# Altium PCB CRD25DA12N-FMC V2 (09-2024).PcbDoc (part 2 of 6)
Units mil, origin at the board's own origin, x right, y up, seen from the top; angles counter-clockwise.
Board outline 8000 x 8000 mil, 6 copper layers (Top Layer, Layer 2, Layer 3, Layer 4, Layer 5, Bottom Layer), stack 91 mil thick; 602 components, 333 nets, 1670 pads, 639 vias.
Unrouted connection lines stored in the file: 1.
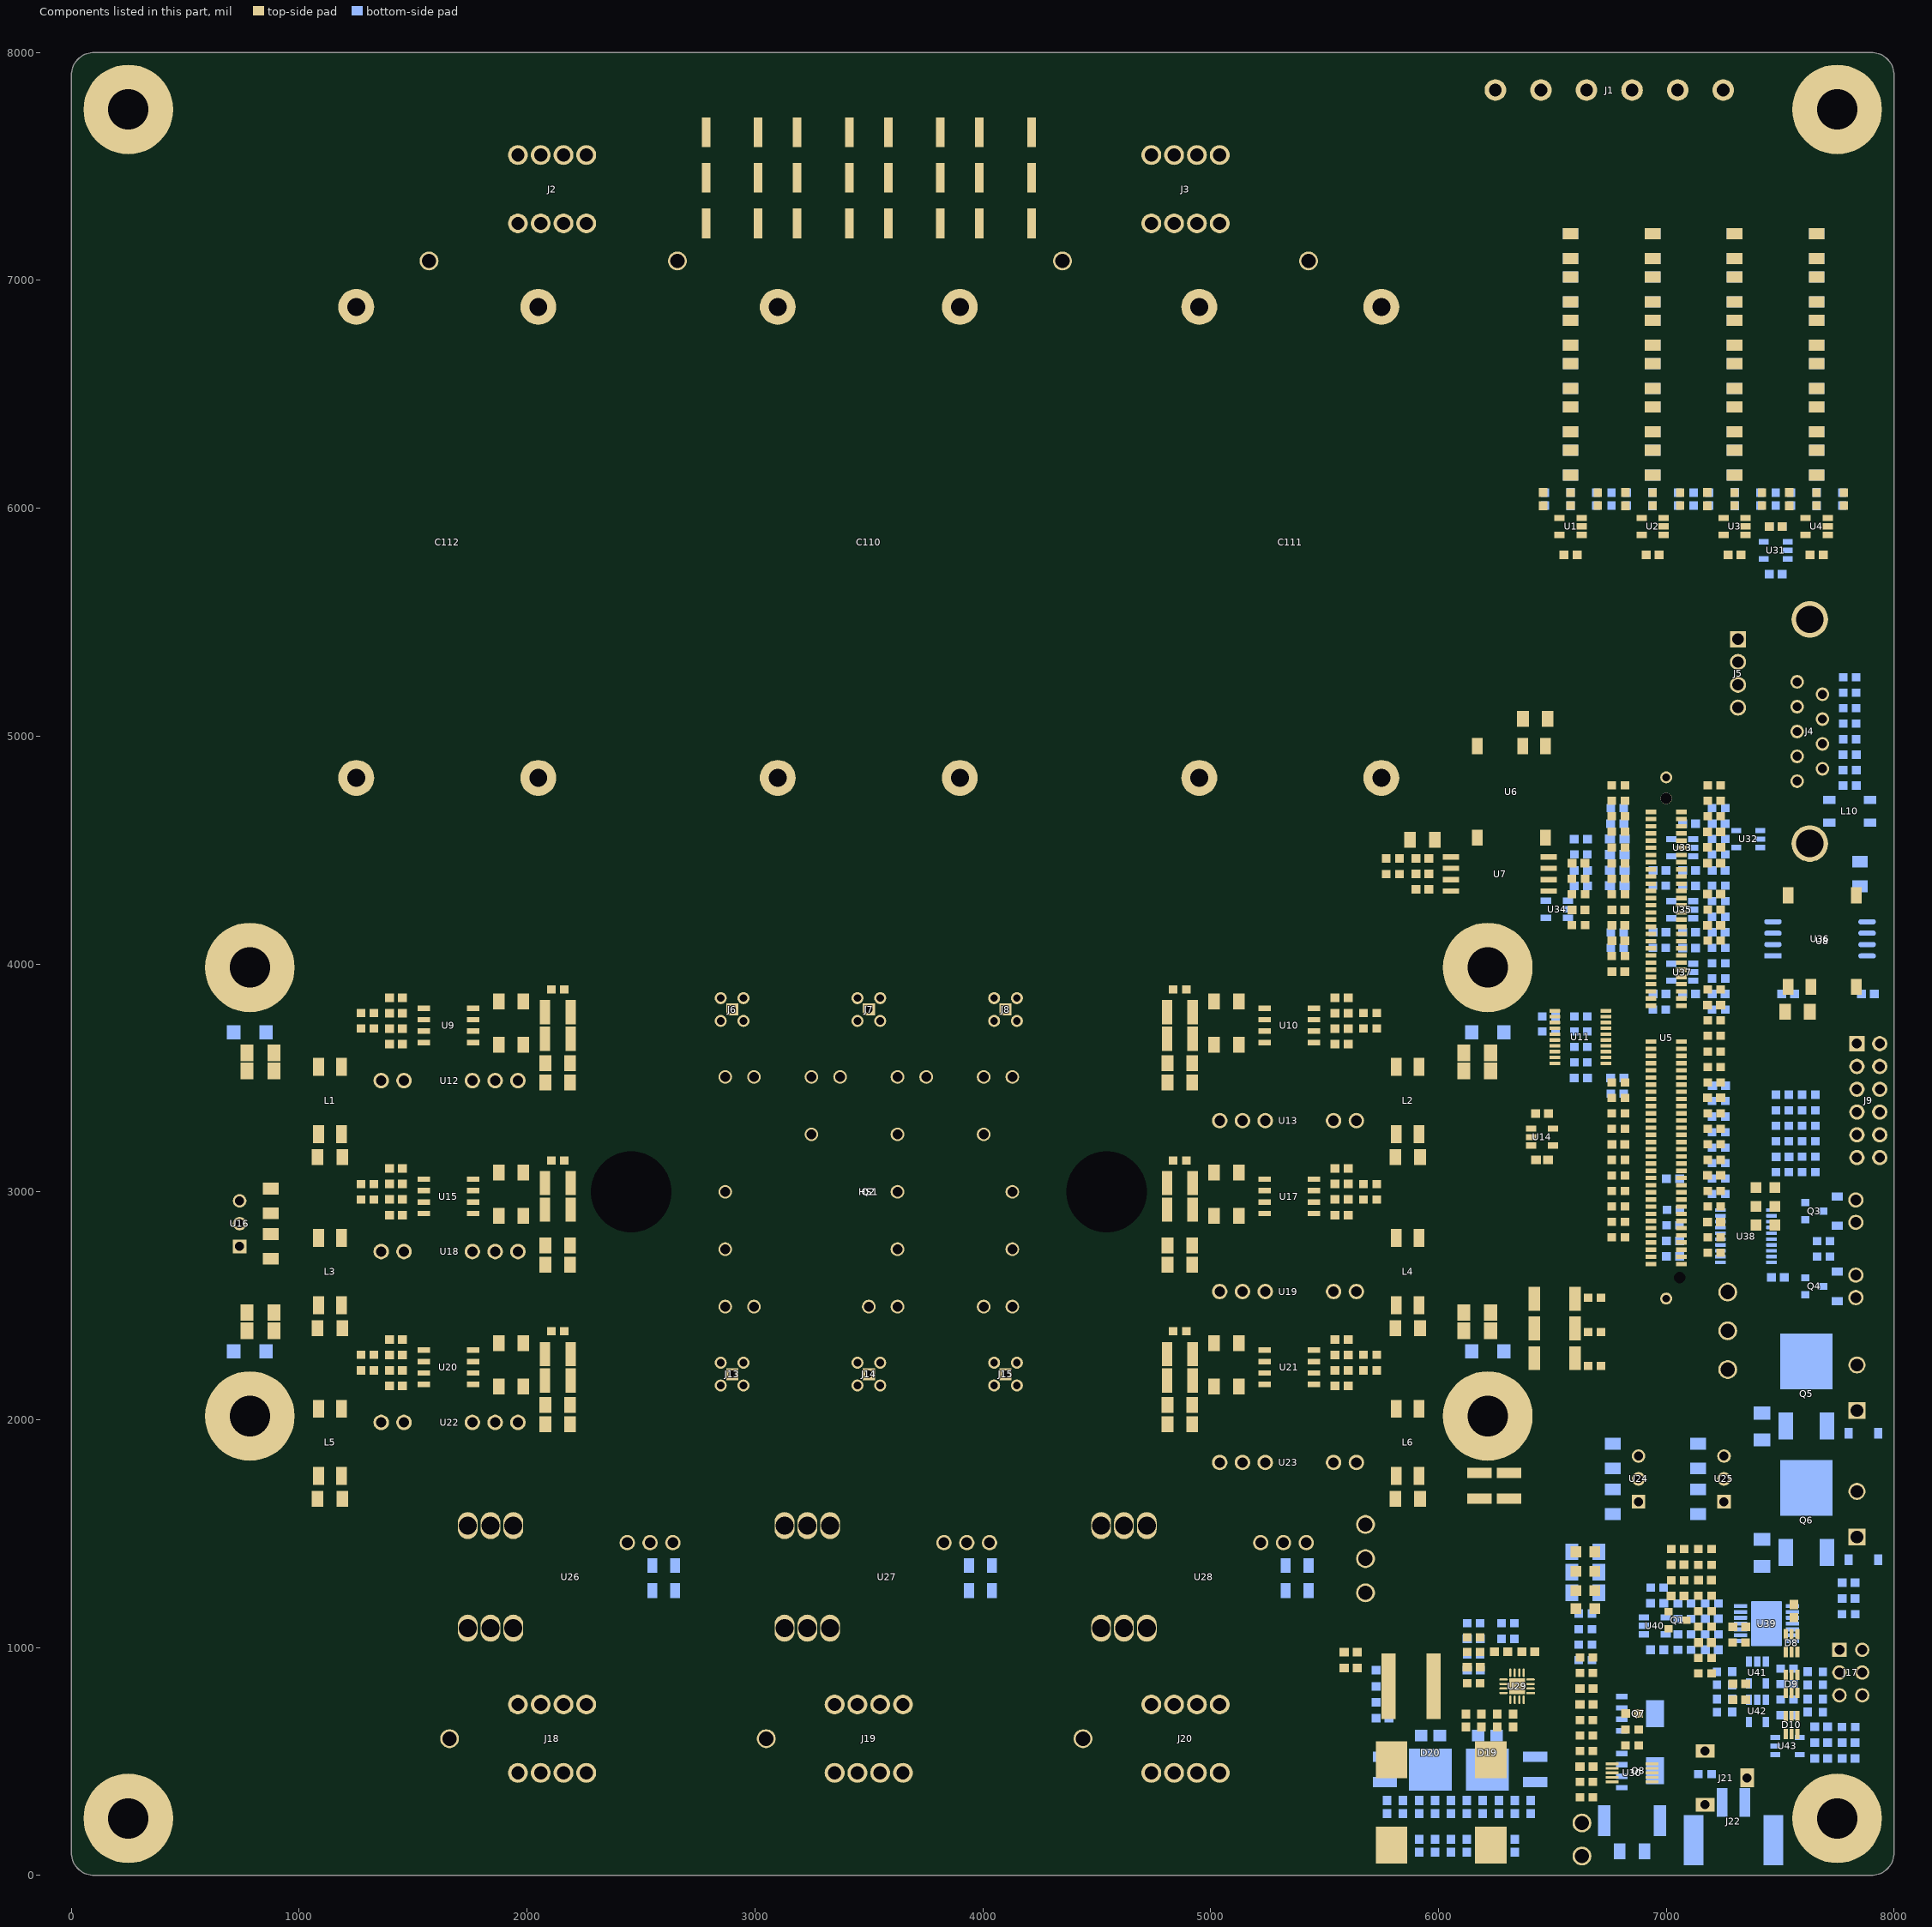
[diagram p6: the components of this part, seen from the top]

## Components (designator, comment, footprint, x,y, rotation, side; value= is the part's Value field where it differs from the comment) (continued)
R196 "RC0603JR-07120RL" FP-MCR03-IPC_B 7805,4986 r0 bottom value=120Ω
R197 "ERJ3EKF1002V" FP-MCR03-IPC_B 7230,4684 r180 bottom value=10kΩ
R198 "ERJ3EKF1002V" FP-MCR03-IPC_B 6785,4684 r0 bottom value=10kΩ
R199 "RT0603DRD071K4L" FP-MCR03-IPC_B 7230,4548 r180 bottom value=1.4kΩ
R200 "RMCF0603FT7K15" FP-MCR03-IPC_B 7230,4480 r180 bottom value=7.15kΩ
R201 "ERA3AEB4021V" FP-MCR03-IPC_B 6625,4480 r0 bottom value=4.02kΩ
R202 "ERA3AEB4021V" FP-MCR03-IPC_B 7230,4343 r0 bottom value=4.02kΩ
R203 "RC0603FR-077K87L" FP-MCR03-IPC_B 6970,4343 r0 bottom value=7.87kΩ
R204 "RT0603DRD071K4L" FP-MCR03-IPC_B 7230,4275 r180 bottom value=1.4kΩ
R205 "RMCF0603FT7K15" FP-MCR03-IPC_B 7230,4207 r180 bottom value=7.15kΩ
R206 "ERJ-3EKF49R9V" FP-MCR03-IPC_B 6785,4139 r0 bottom value=49.9Ω
R207 "ERA3AEB4021V" FP-MCR03-IPC_B 7230,4070 r0 bottom value=4.02kΩ
R208 "RC0603FR-077K87L" FP-MCR03-IPC_B 6970,4070 r0 bottom value=7.87kΩ
R209 "ERJ-3EKF49R9V" FP-MCR03-IPC_B 6785,4070 r0 bottom value=49.9Ω
R210 "RT0603DRD071K4L" FP-MCR03-IPC_B 7230,4003 r180 bottom value=1.4kΩ
R211 "RMCF0603FT7K15" FP-MCR03-IPC_B 7230,3936 r180 bottom value=7.15kΩ
R212 "ERA3AEB4021V" FP-MCR03-IPC_B 7230,3800 r0 bottom value=4.02kΩ
R213 "RC0603FR-077K87L" FP-MCR03-IPC_B 6970,3800 r0 bottom value=7.87kΩ
R214 "RC0603FR-07100KL" FP-MCR03-IPC_B 6625,3770 r180 bottom value=100kΩ
R215 "RC0603FR-07100KL" FP-MCR03-IPC_B 6485,3770 r180 bottom value=100kΩ
R216 "RC0603FR-07100KL" FP-MCR03-IPC_B 6625,3703 r180 bottom value=100kΩ
R217 "RC0603FR-07100KL" FP-MCR03-IPC_B 6485,3703 r180 bottom value=100kΩ
R218 "RC0603FR-07100KL" FP-MCR03-IPC_B 6625,3636 r180 bottom value=100kΩ
R219 "RC0603FR-07100KL" FP-MCR03-IPC_B 6625,3568 r180 bottom value=100kΩ
R220 "ERJ3EKF1002V" FP-MCR03-IPC_B 6785,3430 r180 bottom value=10kΩ
R221 "RC0603FR-13330RL" FP-MCR03-IPC_B 7625,3426 r180 bottom value=330Ω
R222 "RC0603FR-13330RL" FP-MCR03-IPC_B 7510,3426 r180 bottom value=330Ω
R223 "ERJ3EKF1002V" FP-MCR03-IPC_B 7230,3398 r180 bottom value=10kΩ
R224 "RC0603FR-13330RL" FP-MCR03-IPC_B 7625,3358 r180 bottom value=330Ω
R225 "RC0603FR-13330RL" FP-MCR03-IPC_B 7510,3358 r180 bottom value=330Ω
R226 "CRCW06030000Z0EB" FP-MCR03-IPC_B 7230,3330 r180 bottom value=0Ω
R227 "CRCW06030000Z0EB" FP-MCR03-IPC_B 7625,3290 r180 bottom value=0Ω
R228 "ERJ3EKF1002V" FP-MCR03-IPC_B 7510,3290 r0 bottom value=10kΩ
R229 "CRCW06030000Z0EB" FP-MCR03-IPC_B 7230,3262 r180 bottom value=0Ω
R230 "RC0603FR-13330RL" FP-MCR03-IPC_B 7625,3222 r180 bottom value=330Ω
R231 "RC0603FR-13330RL" FP-MCR03-IPC_B 7510,3222 r180 bottom value=330Ω
R232 "CRCW06030000Z0EB" FP-MCR03-IPC_B 7230,3194 r180 bottom value=0Ω
R233 "CRCW06030000Z0EB" FP-MCR03-IPC_B 7625,3154 r180 bottom value=0Ω
R234 "CRCW06030000Z0EB" FP-MCR03-IPC_B 7230,3126 r180 bottom value=0Ω
R235 "ERJ3EKF1002V" FP-MCR03-IPC_B 7625,3086 r0 bottom value=10kΩ
R236 "ERJ3EKF1002V" FP-MCR03-IPC_B 7510,3086 r0 bottom value=10kΩ
R237 "CRCW06030000Z0EB" FP-MCR03-IPC_B 7230,3058 r180 bottom value=0Ω
R238 "CRCW06030000Z0EB" FP-MCR03-IPC_B 7230,2990 r180 bottom value=0Ω
R239 "CRCW060320K0FKTA" FP-MCR03-IPC_B 7031.38,2920 r180 bottom value=20kΩ
R240 "CRCW060320K0FKTA" FP-MCR03-IPC_B 7030,2853 r180 bottom value=20kΩ
R241 "ERJ-3EKF49R9V" FP-MCR03-IPC_B 7690,2784 r0 bottom value=49.9Ω
R242 "ERJ-3EKF49R9V" FP-MCR03-IPC_B 7690,2716 r0 bottom value=49.9Ω
R243 "RC1206FR-07249RL" FP-MCR18-IPC_A 7420,1970 r270 bottom value=249Ω
R244 "RC1206FR-07249RL" FP-MCR18-IPC_A 7420,1415 r270 bottom value=249Ω
R245 "RC1206FR-07249RL" FP-MCR18-IPC_A 6645,1420 r0 bottom value=249Ω
R246 "RC1206FR-07249RL" FP-MCR18-IPC_A 6645,1330 r180 bottom value=249Ω
R247 "ERJ3EKF3901V" FP-MCR03-IPC_B 6960,1263 r0 bottom value=3.9kΩ
R248 "RC1206FR-07249RL" FP-MCR18-IPC_A 6645,1240 r0 bottom value=249Ω
R249 "RC0603FR-07470KL" FP-MCR03-IPC_B 7200,1194 r180 bottom value=470kΩ
R250 "ERA-3AED153V" FP-MCR03-IPC_B 7080,1194 r0 bottom value=15kΩ
R251 "CRCW06034K70FKTA" FP-MCR03-IPC_B 6645,1149 r180 bottom value=4.7kΩ
R252 "ERJ3EKF1002V" FP-MCR03-IPC_B 7800,1146 r180 bottom value=10kΩ
R253 "ERJ3EKF3901V" FP-MCR03-IPC_B 7080,1126 r180 bottom value=3.9kΩ
R254 "RT0603DRE0722K6L" FP-MCR03-IPC_B 6305,1106 r0 bottom value=22.6kΩ
R255 "RT0603DRE072KL" FP-MCR03-IPC_B 6155,1106 r180 bottom value=2kΩ
R256 "CRCW06034K70FKTA" FP-MCR03-IPC_B 6645,1081 r180 bottom value=4.7kΩ
R257 "ERA-3AED153V" FP-MCR03-IPC_B 7200,1058 r180 bottom value=15kΩ
R258 "ERJ3EKF1002V" FP-MCR03-IPC_B 7080,1058 r0 bottom value=10kΩ
R259 "RT0603DRE0734K8L" FP-MCR03-IPC_B 6305,1038 r180 bottom value=34.8kΩ
R260 "CRCW06034K70FKTA" FP-MCR03-IPC_B 6645,1013 r0 bottom value=4.7kΩ
R261 "ERJ3EKF1002V" FP-MCR03-IPC_B 7080,990 r180 bottom value=10kΩ
R262 "RT0603BRD075K36L" FP-MCR03-IPC_B 6155,970 r0 bottom value=5.36kΩ
R263 "CRCW06034K70FKTA" FP-MCR03-IPC_B 6645,945 r0 bottom value=4.7kΩ
R264 "ERJ-PB3B1212V" FP-MCR03-IPC_B 7530,907 r180 bottom value=12.1kΩ
R265 "RC0603FR-0747KL" FP-MCR03-IPC_B 7688,865 r270 bottom value=47kΩ
R266 "ERJ3EKF1002V" FP-MCR03-IPC_B 7222,865 r270 bottom value=10kΩ
R267 "ERJ-PB3B1212V" FP-MCR03-IPC_B 7530,839 r180 bottom value=12.1kΩ
R268 "ERJ-PB3B1212V" FP-MCR03-IPC_B 7530,771 r180 bottom value=12.1kΩ
R269 "RC0603FR-0747KL" FP-MCR03-IPC_B 7688,745 r90 bottom value=47kΩ
R270 "ERJ3EKF1002V" FP-MCR03-IPC_B 7222,745 r270 bottom value=10kΩ
R271 "ERJ-PB3B1212V" FP-MCR03-IPC_B 7530,703 r180 bottom value=12.1kΩ
R272 "ERJ3EKF1002V" FP-MCR03-IPC_B 7800,652 r0 bottom value=10kΩ
R273 "CRCW121010R0FKEAHP" RESC3125X70X40NL20T20 6425,465 r270 bottom value=10Ω
R274 "CRCW121010R0FKEAHP" RESC3125X70X40NL20T20 5765,465 r270 bottom value=10Ω
R275 "RC0603FR-07100KL" FP-MCR03-IPC_B 7170,445 r0 bottom value=100kΩ
R276 "PE2512FKE7W0R01L" FP-RL2512-IPC_A 6850,240 r180 bottom value=10mΩ
TP1 "5010" KSTN-5010_V 1570,7085 r0 top value=RED
TP2 "5010" KSTN-5010_V 2660,7085 r0 top value=RED
TP3 "5011" KSTN-5011_V 4350,7085 r0 top value=BLACK
TP4 "5011" KSTN-5011_V 5430,7085 r0 top value=BLACK
TP5 "5010" KSTN-5010_V 7270,2560 r0 top value=RED
TP6 "5010" KSTN-5010_V 7270,2390 r0 top value=RED
TP7 "5011" KSTN-5011_V 7270,2220 r0 top value=BLACK
TP8 "5010" KSTN-5010_V 5680,1540 r0 top value=RED
TP9 "5010" KSTN-5010_V 5680,1390 r0 top value=RED
TP10 "5011" KSTN-5011_V 5680,1240 r0 top value=BLACK
TP11 "5012" KSTN-5012_V 1660,600 r0 top value=WHITE
TP12 "5012" KSTN-5012_V 3050,600 r0 top value=WHITE
TP13 "5012" KSTN-5012_V 4440,600 r0 top value=WHITE
TP14 "5010" KSTN-5010_V 6630,230 r0 top value=RED
TP15 "5011" KSTN-5011_V 6630,85 r0 top value=BLACK
U1 "AD8615AUJZ-REEL7" ADI-UJ-5_M 6580,5920 r180 top value=N/A
U2 "AD8615AUJZ-REEL7" ADI-UJ-5_M 6940,5920 r180 top value=N/A
U3 "AD8615AUJZ-REEL7" ADI-UJ-5_M 7300,5920 r180 top value=N/A
U4 "AD8615AUJZ-REEL7" ADI-UJ-5_M 7660,5920 r180 top value=N/A
U5 "TMDSCNCD280039C" TMDSCNCD280039C 7000,3675 r90 top locked value=N/A
U6 "R1SE-3.305/H2-R" FP-R1SE-0505-R-MFG 6320,4755 r270 top value=N/A
U7 "AMC1311BDWV" FP-DWV0008A-MFG 6270,4395 r0 top value=N/A
U8 "R1SE-3.305/H2-R" FP-R1SE-0505-R-MFG 7685,4100 r90 top value=N/A
U9 "UCC5350SBD" D0008B_HV 1655,3730 r0 top value=N/A
U10 "UCC5350SBD" D0008B_HV 5345,3730 r180 top value=N/A
U11 "SN74LV541ATPWR" PW0020A_L 6622.8,3678.98 r180 top value=N/A
U12 "MGJ2D121503SC" MGJ2D121509SC 1660,3400 r0 top value=N/A
U13 "MGJ2D121503SC" MGJ2D121509SC 5340,3400 r180 top value=N/A
U14 "MCP6271RT-E/OT" ADI-UJ-5_M 6455,3240 r0 top value=N/A
U15 "UCC5350SBD" D0008B_HV 1655,2980 r0 top value=N/A
U16 "R-78E5.0-1.0" CONV_R-78E5.0-1.0 650,2860 r90 top value=N/A
U17 "UCC5350SBD" D0008B_HV 5345,2980 r180 top value=N/A
U18 "MGJ2D121503SC" MGJ2D121509SC 1660,2650 r0 top value=N/A
U19 "MGJ2D121503SC" MGJ2D121509SC 5340,2650 r180 top value=N/A
U20 "UCC5350SBD" D0008B_HV 1655,2230 r0 top value=N/A
U21 "UCC5350SBD" D0008B_HV 5345,2230 r180 top value=N/A
U22 "MGJ2D121503SC" MGJ2D121509SC 1660,1900 r0 top value=N/A
U23 "MGJ2D121503SC" MGJ2D121509SC 5340,1900 r180 top value=N/A
U24 "R-78E3.3-1.0" CONV_R-78E3.3-1.0 6790,1740 r90 top value=N/A
U25 "R-78E5.0-1.0" CONV_R-78E5.0-1.0 7165,1740 r90 top value=N/A
U26 "LAH 50-P" "LAH 50-P" 2110,1300 r90 top locked value=N/A
U27 "LAH 50-P" "LAH 50-P" 3500,1300 r90 top locked value=N/A
U28 "LAH 50-P" "LAH 50-P" 4890,1300 r90 top locked value=N/A
U29 "LM5157QRTERQ1" FP-RTE0016K-IPC_A 6345,830 r180 top value=N/A
U30 "LTC4368IMS-2#PBF" SOP50P490X110-10N 6850,450 r0 top value=N/A
U31 "REF2033QDDCRQ1" FP-DDC0005A-MFG 7480,5815 r180 bottom value=N/A
U32 "REF2033QDDCRQ1" FP-DDC0005A-MFG 7360,4548 r180 bottom value=N/A
U33 "AD8615AUJZ-REEL7" ADI-UJ-5_M 7070,4510 r180 bottom value=N/A
U34 "MCP6271RT-E/OT" ADI-UJ-5_M 6520,4240 r180 bottom value=N/A
U35 "AD8615AUJZ-REEL7" ADI-UJ-5_M 7070,4238 r180 bottom value=N/A
U36 "ISO1042BQDWVRQ1" FP-DWV0008A-IPC_B 7675,4110 r0 bottom value=N/A
U37 "AD8615AUJZ-REEL7" ADI-UJ-5_M 7070,3964 r180 bottom value=N/A
U38 "SN74LV541ATPWR" PW0020A_L 7350,2805 r0 bottom value=N/A
U39 "ALM2402FQPWPRQ1" FP-PWP0014H-MFG 7440,1105 r0 bottom value=N/A
U40 "AD8615AUJZ-REEL7" ADI-UJ-5_M 6950,1095 r0 bottom value=N/A
U41 "AD8615AUJZ-REEL7" ADI-UJ-5_M 7400,890 r270 bottom value=N/A
U42 "AD8615AUJZ-REEL7" ADI-UJ-5_M 7400,721.77 r270 bottom value=N/A
U43 "REF2033QDDCRQ1" FP-DDC0005A-MFG 7531.85,567.6 r0 bottom value=N/A

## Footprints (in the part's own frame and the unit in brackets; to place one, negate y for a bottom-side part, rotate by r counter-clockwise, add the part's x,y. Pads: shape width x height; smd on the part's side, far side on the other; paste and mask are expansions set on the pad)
1755736 [mm] "THD, 2-Leads, Body 12.16x8.6mm, Pitch 5.08mm"
  rect 1.9x1.9 hole 1.4: 1(-2.54,0)
  round 1.9 hole 1.4: 2(2.54,0)
  silkscreen extent -6.08,-3.81 6.08,4.79, body extent -6.08,-3.8 6.16,4.87, height 12
1755778 [mm] "TERM BLOCK HDR 6POS VERT 5.08MM"
  round 2.4 hole 1.4: 1(-12.7,0) 2(-7.62,0) 3(-2.54,0) 4(2.54,0) 5(7.62,0) 6(12.7,0)
  silkscreen extent -16.24,-3.83 16.24,3.84, body extent -16.24,-3.84 16.24,4.76, height 12
1808190 [mm]
  rect 1.2x3.2 smd: 1(-1.25,4.2) 2(1.25,4.2)
  rect 2.2x5.6 smd: 3(-4.45,0) 4(4.45,0)
  silkscreen extent -3.5,-3.7 3.5,3.5, body extent -5.4,-4 5.2,5.5, height 5
7460307 [mm] "8 Pin Screw Terminal, Power Tap M4 Through Hole"
  round 2.21 hole 1.475: 1(-3.81,3.81) 2(-1.27,3.81) 3(1.27,3.81) 4(3.81,3.81) 5(3.81,-3.81) 6(1.27,-3.81) 7(-1.27,-3.81) 8(-3.81,-3.81)
  Top Layer keep-out region: -8.5,-8.5 8.5,-8.5 8.5,8.5 -8.5,8.5
  Bottom Layer keep-out region: -8.5,-8.5 8.5,-8.5 8.5,8.5 -8.5,8.5
  silkscreen extent -5.2,-5.2 5.2,5.2, body extent -4.5,-4.5 4.5,4.5, height 7
61200621621 [mm] "6 pins, straight, gold plating"
  rect 1.6x1.6 hole 1.1: 1(-2.54,-1.27)
  round 1.6 hole 1.1: 2(-2.54,1.27) 3(0,-1.27) 4(0,1.27) 5(2.54,-1.27) 6(2.54,1.27)
  silkscreen extent -7.74,-4.5 7.74,4.5, body extent -7.64,-4.43 7.64,4.75, height 9.13
74437368220 [mm]
  rect 4.1x3.5 smd: 1(-4.75,0) 2(4.75,0)
  Top Layer keep-out region: -2.7,-5 2.7,-5 2.7,5 -2.7,5
  silkscreen extent -5.5,-5.5 5.5,5.5, body extent -5.5,-5 5.5,5, height 3.7
ADI-UJ-5_M [mm] "SOT23, 5-Leads, Body 2.9x1.6mm, Pitch 0.95mm, IPC Low Density"
  rect 1.15x0.7 smd: 1(-1.225,0.95) 2(-1.225,0) 3(-1.225,-0.95) 4(1.225,-0.95) 5(1.225,0.95)
  silkscreen extent -1.35,-1.45 0.25,1.97, body extent -0.8,-1.45 0.8,1.45, height 1
C4AQQEW5650A3BJ [mm] "CAP FILM 65UF 5% 1.1KVDC RAD"
  round 4 hole 2: 1(-26.25,10.15) 2(-26.25,-10.15) 3(26.25,10.15) 4(26.25,-10.15)
  silkscreen extent -28.75,-22.5 28.75,22.5, body extent -29,-22.71 29.3,22.8, height 65.4
CONN_1881558 [mil]
  round 67 / inner round 60 / far side round 67 hole 47 paste-99999 mask+0: 1(-49.21,0) 2(49.21,0)
  silkscreen extent -141,-159 141,170, body extent -136,-154 136,165, height 398
CONV_R-78E3.3-1.0 [mm]
  rect 1.508x1.508 hole 1: 1(-2.54,-2.25)
  round 1.508 hole 1: 2(0,-2.25) 3(2.54,-2.25)
  silkscreen extent -6.5,-4.25 5.75,4.25, body extent -5.8,-4.25 5.8,4.25, height 9.9
CONV_R-78E5.0-1.0 [mm]
  rect 1.508x1.508 hole 1: 1(-2.54,-2.25)
  round 1.508 hole 1: 2(0,-2.25) 3(2.54,-2.25)
  silkscreen extent -6.5,-4.25 5.75,4.25, body extent -5.8,-4.25 5.8,4.25, height 9.9
CUI-PJ-102B_V [mm] "THD, 3-Leads, Body 14.4x9mm, Height 11mm"
  rect 1.5x2.1 hole 1 slot 1.6 at 90 deg: 1(-3,0) 2(3,0)
  rect 2.1x1.5 hole 1 slot 1.6 at 0 deg: 3(0,4.7)
  silkscreen extent -4.42,-4.5 10.7,4.9, body extent -3.7,-4.5 10.7,4.9, height 11
D0008B_HV [mm]
  rect 1.4x0.6 smd paste+0 mask+0: 1(-2.75,1.905) 2(-2.75,0.635) 3(-2.75,-0.635) 4(-2.75,-1.905) 5(2.75,-1.905) 6(2.75,-0.635) 7(2.75,0.635) 8(2.75,1.905)
  silkscreen extent -3.3,-2.5 0.9,3.35, body extent -3.01,-2.45 3.01,2.45, height 1.63
FM3_SIX-PACK_3PHASE_CRW [mm]
  round 1.524 hole 1.1: DC+_1(-6.4,-6.4) DC+_2(3.2,-6.4) DC+_3(12.8,-6.4) DC-1(-16,0) DC-2(3.2,0) DC-3(16,0) G1(-12.8,-12.8) G2(-16,12.8) G3(-3.2,-12.8) G4(3.2,12.8) G5(6.4,-12.8) G6(16,12.8) NTC1(12.8,-12.8) NTC2(16,-12.8) S1(-16,-12.8) S2(-12.8,12.8) S3(-6.4,-12.8) S4(0,12.8) S5(3.2,-12.8) S6(12.8,12.8) U(-16,6.4) V(3.2,6.4) W(16,6.4)
  round 0 hole 9 unplated: MH1(-26.5,0) MH2(26.5,0)
  Bottom Layer keep-out circle w6.2: c16,12.8 r2
  Bottom Layer keep-out circle w6.2: c-16,12.8 r2
  Bottom Layer keep-out circle w6.2: c-12.8,12.8 r2
  Bottom Layer keep-out circle w6.2: c0,12.8 r2
  Bottom Layer keep-out circle w6.2: c12.8,12.8 r2
  Bottom Layer keep-out circle w6.2: c3.2,12.8 r2
  Bottom Layer keep-out circle w6.2: c16,-12.8 r2
  Bottom Layer keep-out circle w6.2: c12.8,-12.8 r2
  Bottom Layer keep-out circle w6.2: c6.4,-12.8 r2
  Bottom Layer keep-out circle w6.2: c3.2,-12.8 r2
  Bottom Layer keep-out circle w6.2: c-3.2,-12.8 r2
  Bottom Layer keep-out circle w6.2: c-6.4,-12.8 r2
  Bottom Layer keep-out circle w6.2: c-12.8,-12.8 r2
  Bottom Layer keep-out circle w6.2: c-16,-12.8 r2
  Bottom Layer keep-out circle w6.2: c-16,6.4 r2
  Bottom Layer keep-out circle w6.2: c-16,0 r2
  Bottom Layer keep-out circle w6.2: c-6.4,-6.4 r2
  Bottom Layer keep-out circle w6.2: c3.2,-6.4 r2
  Bottom Layer keep-out circle w6.2: c12.8,-6.4 r2
  Bottom Layer keep-out circle w6.2: c16,0 r2
  Bottom Layer keep-out circle w6.2: c16,6.4 r2
  Bottom Layer keep-out circle w6.2: c3.2,6.4 r2
  Bottom Layer keep-out circle w6.2: c3.2,0 r2
  silkscreen extent -31.52,-16.88 31.52,16.88, body extent -31.4,-16.9 31.4,16.9, height 11.98
FP-73415-1471-MFG [mm]
  rect 1.34x1.34 hole 0.84 paste-2539.97 mask+0: 1(0.01,0)
  round 1.34 hole 0.84 paste-2539.97 mask+0: 2(-1.27,1.27) 3(1.27,1.27) 4(-1.27,-1.27) 5(1.27,-1.27)
  silkscreen extent -2.54,-1.82 1.82,1.82, body extent -2.04,-2.04 2.04,2.04, height 0.25
FP-61301221121-MFG [mm]
  rect 1.7x1.7 hole 1.1 paste-2539.97 mask+0: 1(-6.35,-1.27)
  round 1.7 hole 1.1 paste-2539.97 mask+0: 2(-6.35,1.27) 3(-3.81,-1.27) 4(-3.81,1.27) 5(-1.27,-1.27) 6(-1.27,1.27) 7(1.27,-1.27) 8(1.27,1.27) 9(3.81,-1.27) 10(3.81,1.27) 11(6.35,-1.27) 12(6.35,1.27)
  silkscreen extent -8.38,-2.62 7.77,2.62, body extent -7.87,-2.72 7.87,2.72, height 0.25
FP-APTR3216SECK-MFG [mm]
  rect 1.5x1.6 smd paste+0 mask+0: 1(-1.8,0) 2(1.8,0)
  silkscreen extent -3.3,-1.4 1.9,1.4, body extent -1.6,-0.8 1.6,0.8, height 1.1
FP-C0603C-CF-IPC_B [mil]
  rect 39.63x37.73 smd paste+0 mask+0: 1(-28.58,0) 2(28.58,0)
  silkscreen extent -48,-35 48,35, body extent -31,-16 31,16, height 34
FP-CL31-IPC_B [mil]
  rect 51.4x69.22 smd paste+0 mask+0: 1(-54.19,0) 2(54.19,0)
  silkscreen extent -17,-35 17,35, body extent -63,-31 63,31, height 55
FP-CL31-IPC_C [mil]
  rect 43.52x65.28 smd paste+0 mask+0: 1(-50.25,0) 2(50.25,0)
  silkscreen extent -17,-34 17,34, body extent -63,-31 63,31, height 55
FP-CRCW2010-e3-IPC_B [mil]
  rect 51.42x104.65 smd paste+0 mask+0: 1(-89.61,0) 2(89.61,0)
  silkscreen extent -49,-49 49,49, body extent -125,-62 125,62, height 10
FP-CRGP2512-IPC_C [mil]
  rect 37.72x130.17 smd paste+0 mask+0: 1(-114.25,0) 2(114.25,0)
  silkscreen extent -84,-67 84,67, body extent -125,-63 125,63, height 26
FP-DDC0005A-MFG [mm]
  rect 1.1x0.6 smd paste+0 mask+0: 1(-1.35,0.95) 2(-1.35,0) 3(-1.35,-0.95) 4(1.35,-0.95) 5(1.35,0.95)
  silkscreen extent -2.6,-1.53 0.87,1.53, body extent -1.4,-1.45 1.4,1.45, height 1.1
FP-DLW43-0_2-t2_6-e0_6-MFG [mm]
  rect 1.35x0.9 smd paste+0 mask+0: 1(-2.275,-1.25) 2(2.275,-1.25) 3(2.275,1.25) 4(-2.275,1.25)
  silkscreen extent -3.65,-1.7 2.35,1.7, body extent -2.35,-1.7 2.35,1.7, height 2.8
FP-DWV0008A-IPC_B [mil]
  rect 76.93x22.92 smd paste+0 mask+0: 1(-206.71,75)
  rrect100% 76.93x22.92 smd paste+0 mask+0: 2(-206.71,25) 3(-206.71,-25) 4(-206.71,-75) 5(206.71,-75) 6(206.71,-25) 7(206.71,25) 8(206.71,75)
  silkscreen extent -283,-115 149,115, body extent -226,-115 226,115, height 110
FP-DWV0008A-MFG [mm]
  rect 1.8x0.6 smd paste+0 mask+0: 1(-5.45,1.905) 2(-5.45,0.635) 3(-5.45,-0.635) 4(-5.45,-1.905) 5(5.45,-1.905) 6(5.45,-0.635) 7(5.45,0.635) 8(5.45,1.905)
  silkscreen extent -7.2,-2.98 3.8,2.98, body extent -6.45,-3.22 6.45,3.22, height 0.25
FP-GCM188-0_1-IPC_A [mil]
  rect 45.62x39.85 smd paste+0 mask+0: 1(-32.55,0) 2(32.55,0)
  silkscreen extent -55,-36 55,36, body extent -31,-16 31,16, height 35
FP-LTST-C171GKT-MFG [mm]
  rect 1.2x1.2 smd paste+0 mask+0: 1(-1.05,0) 2(1.05,0)
  silkscreen extent -2.37,-1.05 1.05,1.05, body extent -1.75,-0.77 1.75,0.77, height 0.25
FP-LTST-C171GKT-MFG-RED [mm]
  rect 1.2x1.2 smd paste+0 mask+0: 1(-1.05,0) 2(1.05,0)
  silkscreen extent -2.37,-1.05 1.05,1.05, body extent -1,-0.63 1,0.63, height 0.8
FP-LTST-C171GKT-MFG-YELLOW [mm]
  rect 1.2x1.2 smd paste+0 mask+0: 1(-1.05,0) 2(1.05,0)
  silkscreen extent -2.37,-1.05 1.05,1.05, body extent -1,-0.63 1,0.63, height 0.8
FP-MCR03-IPC_B [mil]
  rect 37.72x35.91 smd paste+0 mask+0: 1(-28.62,0) 2(28.62,0)
  silkscreen extent -47,-34 47,34, body extent -31,-16 31,16, height 22
FP-MCR18-IPC_A [mil]
  rect 57.31x73.16 smd paste+0 mask+0: 1(-59.1,0) 2(59.1,0)
  silkscreen extent -19,-37 19,37, body extent -107,-56 107,56, height 10
FP-NCU18-0_15-IPC_B [mil]
  rect 43.55x37.73 smd paste+0 mask+0: 1(-26.62,0) 2(26.62,0)
  silkscreen extent -48,-35 48,35, body extent -58,-29 58,29, height 10
FP-PowerDI5060-8-MFG [mm]
  rect 0.61x1.27 smd paste+0 mask+0: 1(-1.905,-2.67) 2(-0.635,-2.67) 3(0.635,-2.67) 4(1.905,-2.67)
  rect 3x2 smd paste+0 mask+0: 5(0,1.05)
  Top Layer region: 2.05,-1.215 -2.05,-1.215 -2.05,-1.035 -2.805,-1.035 -2.805,-0.435 -2.05,-0.435 -2.05,1.39 -2.805,1.39 -2.805,1.99 -2.05,1.99 -2.05,2.285 -2.21,2.285 -2.21,3.305 -1.6,3.305 -1.6,2.595 -0.94,2.595 -0.94,3.305 -0.33,3.305 -0.33,2.595 0.33,2.595 0.33,3.305 0.94,3.305 0.94,2.595 1.6,2.595 1.6,3.305 2.21,3.305 2.21,2.285 2.05,2.285 2.05,1.99 2.805,1.99 2.805,1.39 2.05,1.39 2.05,-0.435 2.805,-0.435 2.805,-1.035 2.05,-1.035
  silkscreen extent -3.2,-2.73 2.55,-1.59, body extent -2.58,-3.08 2.58,3.08, height 1.15
FP-PSMC_TO-277A-MFG [mm]
  rect 4.8x4.72 smd paste+0 mask+0: 1(0,1.04)
  rect 1.4x1.27 smd paste+0 mask+0: 2(-1.04,-2.765) 3(1.04,-2.765)
  silkscreen extent -2.22,-3.08 2.22,-1.7, body extent -2.3,-3.25 2.3,3.25, height 1.21
FP-PWP0014H-MFG [mm]
  rrect22% 1.5x0.45 smd paste+0 mask+0: 1(-2.9,1.95) 2(-2.9,1.3) 3(-2.9,0.65) 4(-2.9,0) 5(-2.9,-0.65) 6(-2.9,-1.3) 7(-2.9,-1.95) 8(2.9,-1.95) 9(2.9,-1.3) 10(2.9,-0.65) 11(2.9,0) 12(2.9,0.65) 13(2.9,1.3) 14(2.9,1.95)
  rrect3% 3.4x5 smd paste-1000 mask-1000: 15(0,0)
  silkscreen extent -2.25,-2.6 2.25,2.6, body extent -3.2,-2.5 3.2,2.5, height 1.2
FP-R1SE-0505-R-MFG [mm]
  rect 1.8x1.2 smd paste+0 mask+0: 1(-5.1,3.81) 2(-5.1,1.27) 4(-5.1,-3.81) 5(5.1,-3.81) 8(5.1,3.81)
  silkscreen extent -5.35,-6.5 5.35,6.5, body extent -6.1,-6.6 6.1,6.6, height 0.25
FP-RL2512-IPC_A [mil]
  rect 53.47x136.15 smd paste+0 mask+0: 1(-122.13,0) 2(122.13,0)
  silkscreen extent -84,-68 84,68, body extent -123,-63 127,63, height 26
FP-RTE0016K-IPC_A [mm]
  rect 0.949x0.239 smd paste+0 mask+0: 1(-1.505,0.75)
  rrect100% 0.949x0.239 smd paste+0 mask+0: 2(-1.505,0.25) 3(-1.505,-0.25) 4(-1.505,-0.75) 9(1.505,-0.75) 10(1.505,-0.25) 11(1.505,0.25) 12(1.505,0.75)
  rrect100% 0.239x0.949 smd paste+0 mask+0: 5(-0.75,-1.505) 6(-0.25,-1.505) 7(0.25,-1.505) 8(0.75,-1.505) 13(0.75,1.505) 14(0.25,1.505) 15(-0.25,1.505) 16(-0.75,1.505)
  rect 1.76x1.76 smd paste-1000 mask+0: 17(0,0)
  silkscreen extent -2.02,-1.5 1.5,1.5, body extent -2.48,-2.48 2.48,2.48, height 0.25
FP-SOT23-MFG [mm]
  rect 0.9x0.8 smd paste+0 mask+0: 1(-1,0.95) 2(-1,-0.95) 3(1,0)
  silkscreen extent -0.18,-1.5 0.7,1.5, body extent -1.2,-1.45 1.2,1.45, height 1.1
KSTN-5010_V [mm] "Test Point, Dia 3.17mm"
  round 2.1 hole 1.6: 1(0,0)
  silkscreen extent -1.59,-1.58 1.59,1.58, body extent -1.59,-1.59 1.59,1.59, height 8.13
KSTN-5011_V [mm] "Test Point, Dia 3.17mm"
  round 2.1 hole 1.6: 1(0,0)
  silkscreen extent -1.59,-1.58 1.59,1.58, body extent -1.59,-1.59 1.59,1.59, height 8.13
KSTN-5012_V [mm] "Test Point, Dia 3.17mm"
  round 2.1 hole 1.6: 1(0,0)
  silkscreen extent -1.59,-1.58 1.59,1.58, body extent -1.59,-1.59 1.59,1.59, height 8.13
L717SDE09PA4CH4RC309 [mm] "CONN D-SUB PLUG 9POS R/A SLDR"
  round 1.508 hole 1: 1(-5.54,1.42) 2(-2.77,1.42) 3(0,1.42) 4(2.77,1.42) 5(5.54,1.42) 6(-4.155,-1.42) 7(-1.385,-1.42) 8(1.385,-1.42) 9(4.155,-1.42)
  round 4.066 hole 3.05: 10(-12.495,0) 11(12.495,0)
  silkscreen extent -15.7,-8.5 15.7,3.4, body extent -15.4,-15.6 15.41,3, height 12.55
"LA 6 150 12" [mm]
  round 10 hole 4.5: 1(-69,25) 2(69,25) 3(-69,-25) 4(69,-25)
  body extent -104.53,-31.05 74.97,30.95, height 86.05
"LAH 50-P" [mil]
  oval 118.74x86.61 hole 78.74 mask+7.87: 1(235,370) 2(235,270) 3(235,170) 5(-215,270) 6(-215,170)
  oval 118.74x86.61 hole 78.74 paste-99999 mask+7.87: 4(-215,370)
  round 67.24 hole 47.24: 7(160,-330) 8(160,-430) 9(160,-530)
  silkscreen extent -285,-635 305,675, body extent -284,-636 304,675, height 790
MGJ2D121509SC [mm]
  round 1.725 hole 1.15: 1(-7.62,2.23) 2(-5.08,2.23) 5(2.54,2.23) 6(5.08,2.23) 7(7.62,2.23)
  silkscreen extent -10.52,-4.9 9.75,4.9, body extent -9.9,-5.09 9.6,4.73, height 13.09
MH_M4_P [mm] "M4 plated mounting hole"
  round 10 hole 4.5: 1(0,0)
  body extent -4,-4.62 4,4.62
ONSC-DPAK-3-369C-01_V [mm] "DPAK, 3-Leads, Body 6.54x6.095mm, Pitch 2.29mm"
  rect 3x1.6 smd: 1(-4.4,2.29) 3(-4.4,-2.29)
  rect 6.2x5.8 smd: 4(2.8,0)
  silkscreen extent -4.52,-3.27 -0.45,3.77, body extent -1.6,-3.27 4.49,3.27, height 2.38
ONSC-SOD-123FL-2-498-01_V [mm] "SOD, 2-Leads, Body 2.7x1.65mm"
  rect 0.91x1.22 smd: 1(-1.635,0) 2(1.635,0)
  silkscreen extent -0.78,-0.82 0.78,0.82, body extent -1.35,-0.82 1.35,0.82, height 1
ONSC-SOT-23-3-318-08_V [mm] "SOT23, 3-Leads, Body 2.92x1.3mm, Pitch 0.95mm"
  rect 0.9x0.8 smd: 1(-1,0.95) 2(-1,-0.95) 3(1,0)
  silkscreen extent -1.12,-1.46 0.65,2.02, body extent -0.65,-1.46 0.65,1.46, height 1.11
PW0020A_L [mm] "SOP, 20-Leads, Body 6.6x4.5mm, Pitch 0.65mm, IPC High Density"
  rrect25% 1.2x0.4 smd: 1(-2.85,2.925) 2(-2.85,2.275) 3(-2.85,1.625) 4(-2.85,0.975) 5(-2.85,0.325) 6(-2.85,-0.325) 7(-2.85,-0.975) 8(-2.85,-1.625) 9(-2.85,-2.275) 10(-2.85,-2.925) 11(2.85,-2.925) 12(2.85,-2.275) 13(2.85,-1.625) 14(2.85,-0.975) 15(2.85,-0.325) 16(2.85,0.325) 17(2.85,0.975) 18(2.85,1.625) 19(2.85,2.275) 20(2.85,2.925)
  silkscreen extent -2.98,-3.3 1.85,3.8, body extent -3.21,-3.25 3.21,3.25, height 1
RESC3125X70X40NL20T20 [mm] "Chip Resistor, 2-Leads, Body 3.10x2.50mm, IPC Medium Density"
  rect 1.15x2.7 smd: 1(-1.425,0) 2(1.425,0)
  silkscreen extent -0.45,-1.25 0.45,1.25, body extent -1.65,-1.35 1.65,1.35, height 0.7
RESC3216X65X50NL15T25 [mm] "Chip Resistor, 2-Leads, Body 3.20x1.60mm, IPC Medium Density"
  rect 1.25x1.75 smd: 1(-1.4,0) 2(1.4,0)
  silkscreen extent -0.4,-0.77 0.4,0.77, body extent -1.68,-0.87 1.68,0.87, height 0.65
SOP50P490X110-10N [mm]
  rect 1.425x0.3 smd: 1(-2.212,1) 2(-2.212,0.5) 3(-2.212,0) 4(-2.212,-0.5) 5(-2.212,-1) 6(2.212,-1) 7(2.212,-0.5) 8(2.212,0) 9(2.212,0.5) 10(2.212,1)
  silkscreen extent -2.92,-1.5 1.15,1.5, body extent -2.45,-1.5 2.45,1.5, height 1.1
SOT65P222X120-6N [mm]
  rect 1.15x0.45 smd: 1(-1,0.65) 2(-1,0) 3(-1,-0.65) 4(1,-0.65) 5(1,0) 6(1,0.65)
  silkscreen extent -1.58,-1 0.08,1.22, body extent -1.11,-1 1.11,1, height 1.2
TECO-640456-4 [mm] "Through Hole, 4-Leads, Body 10.16x5.72mm, Pitch 2.54mm"
  rect 1.8x1.8 hole 1.27 paste-2539.97: 1(3.81,0)
  round 1.8 hole 1.27 paste-2539.97: 2(1.27,0) 3(-1.27,0) 4(-3.81,0)
  silkscreen extent -5.08,-2.54 5.86,3.18, body extent -5.08,-2.54 5.08,3.18, height 10.03
TMDSCNCD280039C [mm]
  rect 0.5x1.2 smd paste+0 mask+0: 1(25.2,1.7) 2(25.2,-1.7) 3(24.4,1.7) 4(24.4,-1.7) 5(23.6,1.7) 6(23.6,-1.7) 7(22.8,1.7) 8(22.8,-1.7) 9(22,1.7) 10(22,-1.7) 11(21.2,1.7) 12(21.2,-1.7) 13(20.4,1.7) 14(20.4,-1.7) 15(19.6,1.7) 16(19.6,-1.7) 17(18.8,1.7) 18(18.8,-1.7) 19(18,1.7) 20(18,-1.7) 21(17.2,1.7) 22(17.2,-1.7) 23(16.4,1.7) 24(16.4,-1.7) 25(15.6,1.7) 26(15.6,-1.7) 27(14.8,1.7) 28(14.8,-1.7) 29(14,1.7) 30(14,-1.7) 31(13.2,1.7) 32(13.2,-1.7) 33(12.4,1.7) 34(12.4,-1.7) 35(11.6,1.7) 36(11.6,-1.7) 37(10.8,1.7) 38(10.8,-1.7) 39(10,1.7) 40(10,-1.7) 41(9.2,1.7) 42(9.2,-1.7) 43(8.4,1.7) 44(8.4,-1.7) 45(7.6,1.7) 46(7.6,-1.7) 47(6.8,1.7) 48(6.8,-1.7) 49(6,1.7) 50(6,-1.7) 51(5.2,1.7) 52(5.2,-1.7) 53(4.4,1.7) 54(4.4,-1.7) 55(3.6,1.7) 56(3.6,-1.7) 57(-0.4,1.7) 58(-0.4,-1.7) 59(-1.2,1.7) 60(-1.2,-1.7) 61(-2,1.7) 62(-2,-1.7) 63(-2.8,1.7) 64(-2.8,-1.7) 65(-3.6,1.7) 66(-3.6,-1.7) 67(-4.4,1.7) 68(-4.4,-1.7) 69(-5.2,1.7) 70(-5.2,-1.7) 71(-6,1.7) 72(-6,-1.7) 73(-6.8,1.7) 74(-6.8,-1.7) 75(-7.6,1.7) 76(-7.6,-1.7) 77(-8.4,1.7) 78(-8.4,-1.7) 79(-9.2,1.7) 80(-9.2,-1.7) 81(-10,1.7) 82(-10,-1.7) 83(-10.8,1.7) 84(-10.8,-1.7) 85(-11.6,1.7) 86(-11.6,-1.7) 87(-12.4,1.7) 88(-12.4,-1.7) 89(-13.2,1.7) 90(-13.2,-1.7) 91(-14,1.7) 92(-14,-1.7) 93(-14.8,1.7) 94(-14.8,-1.7) 95(-15.6,1.7) 96(-15.6,-1.7) 97(-16.4,1.7) 98(-16.4,-1.7) 99(-17.2,1.7) 100(-17.2,-1.7) 101(-18,1.7) 102(-18,-1.7) 103(-18.8,1.7) 104(-18.8,-1.7) 105(-19.6,1.7) 106(-19.6,-1.7) 107(-20.4,1.7) 108(-20.4,-1.7) 109(-21.2,1.7) 110(-21.2,-1.7) 111(-22,1.7) 112(-22,-1.7) 113(-22.8,1.7) 114(-22.8,-1.7) 115(-23.6,1.7) 116(-23.6,-1.7) 117(-24.4,1.7) 118(-24.4,-1.7) 119(-25.2,1.7) 120(-25.2,-1.7)
  round 1.34 hole 0.84 paste-2539.97 mask+0: 121(-29.05,0) 122(29.05,0)
  round 0 hole 1.27 unplated paste-2539.97 mask+0: ""(-26.7,-1.5)
  round 1.27 hole 1.27 unplated paste-2539.97 mask+0: ""(26.7,0)
  silkscreen extent -33.55,-4.25 33.55,3.56, body extent -33.87,-4.89 34.67,5.68, height 57.35
WE-SL2 [mm] "SMD Inductor, 4-Leads, Body 6.3 x 9.5 mm"
  rect 2x1.2 smd: 1(-3.75,1.27) 2(-3.75,-1.27) 3(3.75,-1.27) 4(3.75,1.27)
  silkscreen extent -4.7,-3.18 4.7,3.18, body extent -4.6,-3 4.6,3, height 5
WE-XHMI_8080_L8.8W8.3H7.8 [mm] "SMT Power Inductor, 2-Leads, body 8.8x8.3mm"
  rect 7.35x1.6 smd: 1(0,2.5) 2(0,-2.5)
  Top Layer keep-out region: -4.4,1.5 4.4,1.5 4.4,-1.5 -4.4,-1.5
  silkscreen extent -4.5,-4.25 4.5,4.25, body extent -4.4,-4.15 4.4,4.15, height 7.8

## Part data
C1 C21 C22 C24 C25 C104 C116 C119 C130 C137 C143 C166: "CAP CER 4700PF 25V 10% X7R 0603", Capacitance=4.7nF, Case Code (Imperial)=0603, Case Code (Metric)=1608, Dielectric=X7R, Dielectric Material=Ceramic, Manufacturer=KEMET, Manufacturer Part Number=C0603C472K3RACTU, Max Operating Temperature=125°C, Min Operating Temperature=-55°C, Package Quantity=1, Supplier Part Number 1=67AH9250, Tolerance=10%, Voltage Rating=25V
C2 C3 C4 C90 C94 C113 C114 C115: "CAP CER 10000PF 25V X7R 0603", Capacitance=10nF, Case Code (Imperial)=0603, Case Code (Metric)=1608, Manufacturer=SAMSUNG, Max Operating Temperature=125°C, Min Operating Temperature=-55°C, Ratings=AEC-Q200, Tolerance=10%, Voltage Rating=25V
C5 C6 C7 C8 C9 C11 C13 C15 C16 C17 C18 C45 C46 C89 C92 C100 C102 C117 C118 C123 C135 C136 C140 C141 C142 C150 C151 C152 C161 C169 C170 C180 C182 C183 C184: library part CMP-2006-03057-2, "CAP CER 0.1UF 25V X7R 0603", Capacitance=0.10μF, Manufacturer=KEMET, Package=0603, Temperature="-55°C to +125°C", Temperature Characteristic=X7R, Temperature Coefficient=30ppm/°C, Temperature Range High=+125°C, Temperature Range Low=-55°C, Tolerance=0.1, Voltage Rating=25V
C10 C12 C28 C29 C31 C36 C37 C40 C41 C42 C43 C47 C48 C51 C52 C56 C59 C60 C64 C65 C66 C67 C68 C69 C70 C73 C74 C79 C80 C83 C84 C85 C86 C87 C88 C128 C154 C155 C156 C157 C203: library part CMP-13271-001434-1, "CAP CER 10UF 25V X7R 1206", Capacitance=10μF, Case Code (Imperial)=1206, Case Code (Metric)=3216, Dielectric=X7R, Manufacturer=SAMSUNG, Max Operating Temperature=125°C, Min Operating Temperature=-55°C, Package Quantity=1, Tolerance=10%, Voltage Rating=25V
C14 C26 C27 C38 C39 C49 C50 C61 C62 C71 C72 C81 C82 C126 C147 C153: "CAP CER 2.2UF 50V X5R 0603", Capacitance=2.2μF, Case Code (Imperial)=0603, Case Code (Metric)=1608, Manufacturer=MURATA, Max Operating Temperature=85°C, Min Operating Temperature=-55°C, Ratings=AEC-Q200, Tolerance=20%, Voltage Rating=50V
C19 C23 C91 C99: library part CMP-2006-03716-2, "CAP CER 1000PF 50V X7R 0603", Capacitance=1nF, Manufacturer=KEMET, Package=0603, Temperature="-55°C to +125°C", Temperature Characteristic=X7R, Temperature Coefficient=30ppm/°C, Temperature Range High=+125°C, Temperature Range Low=-55°C, Tolerance=0.1, Voltage Rating="50 V"
C20 C133 C165 C174 C177 C181: library part CMP-03020-020944-2, "CAP CER 330PF 250V C0G/NP0 0603", Capacitance=330pF, Manufacturer=KEMET, Package=0603, Temperature="-55°C to +125°C", Temperature Characteristic=C0G, Temperature Coefficient=30ppm/°C, Temperature Range High=+125°C, Temperature Range Low=-55°C, Tolerance=0.05, Voltage Rating="250 V"
C30 C32 C33 C34 C35 C44 C53 C54 C55 C57 C58 C63 C75 C76 C77 C78 C109 C122 C124 C146 C148 C149: "CAP CER 56PF 50V C0G/NP0 0603", Capacitance=56pF, Case Code (Imperial)=0603, Case Code (Metric)=1608, Dielectric=C0G, Manufacturer=SAMSUNG, Max Operating Temperature=125°C, Min Operating Temperature=-55°C, Package Quantity=1, Temperature Coefficient=30ppm/°C, Tolerance=5%, Voltage=50V
C93 C120 C121 C167: "CAP CER 18PF 50V C0G/NP0 0603", Capacitance=18pF, Case Code (Imperial)=0603, Case Code (Metric)=1608, Dielectric=C0G, Dielectric Material=Ceramic, Insulation Resistance=100GR, Manufacturer="KYOCERA AVX", Max Operating Temperature=125°C, Min Operating Temperature=-55°C, Package Quantity=1, Supplier Part Number 1=1349617, Temperature Coefficient=30ppm/°C, Tolerance=5%, Voltage=50V
C95: "CAP CER 220PF 100V C0G/NP0 0603", Capacitance=220pF, Case Code (Imperial)=0603, Case Code (Metric)=1608, Dielectric=C0G, Manufacturer=MURATA, Max Operating Temperature=125°C, Min Operating Temperature=-55°C, Package Quantity=1, Ratings=AEC-Q200, Supplier Part Number 1=81-GCM1885C2A221J16D, Temperature Coefficient=30ppm/°C, Tolerance=5%, Voltage=100V
C96 C131 C132 C138 C139 C144 C145: "CAP CER 100PF 50V C0G/NP0 0603", Capacitance=100pF, Case Code (Imperial)=0603, Case Code (Metric)=1608, Dielectric=C0G, Manufacturer=SAMSUNG, Max Operating Temperature=125°C, Min Operating Temperature=-55°C, Package Quantity=1, Supplier Part Number 1=7665130, Temperature Coefficient=300ppm/°C, Tolerance=5%, Voltage=50V
C97 C101: "CAP CER 10000PF 100V X7R 0603", Capacitance=10nF, Case Code (Imperial)=0603, Case Code (Metric)=1608, Dielectric=X7R, Manufacturer=MURATA, Max Operating Temperature=125°C, Min Operating Temperature=-55°C, Package Quantity=1, Ratings=AEC-Q200, Supplier Part Number 1=81-GCM188R72A103KA7D, Tolerance=10%, Voltage=100V
C98: "CAP CER 0.068UF 50V X7R 0603", Capacitance=68nF, Case Code (Imperial)=0603, Case Code (Metric)=1608, Dielectric=X7R, Manufacturer=TDK, Max Operating Temperature=125°C, Min Operating Temperature=-55°C, Package Quantity=4000, Ratings=AEC-Q200, Supplier Part Number 1=445-5665-1-ND, Tolerance=10%, Voltage Rating=50V
C103 C188 C191: "CAP CER 1UF 35V X7R 0603", Capacitance=1μF, Case Code (Imperial)=0603, Case Code (Metric)=1608, Dielectric=X7R, Manufacturer=TDK, Max Operating Temperature=125°C, Min Operating Temperature=-55°C, Package Quantity=4000, Ratings=AEC-Q200, Supplier Part Number 1=68AH9307, Tolerance=10%, Voltage Rating=35V
C105 C106 C107 C108 C175 C178 C179 C186 C187 C192 C193 C195 C196 C197 C198 C199 C200 C201 C202: "CAP CER 10UF 35V X5R 0603", Capacitance=10μF, Case Code (Imperial)=0603, Case Code (Metric)=1608, Dielectric=X5R, Manufacturer=MURATA, Max Operating Temperature=85°C, Min Operating Temperature=-55°C, Supplier Part Number 1=81-GRM188R6YA106MA3D, Tolerance=20%, Voltage Rating=35V
C110 C111 C112: "CAP FILM 65UF 5% 1.1KVDC RAD", Capacitance=65µF, Manufacturer=KEMET, Package=RADIAL, Supplier Part Number 1=399-C4AQQEW5650A3BJ-ND, Voltage=1.1kV
C125 C127 C129 C134: library part CMP-06035-043171-1, "CAP CER 0.27UF 16V X7R 0603", Capacitance=0.27μF, Dielectric=X7R, Manufacturer=MURATA, Package=0603, Tolerance=10%, Voltage Rating (DC)=16V
C158 C159 C160 C162 C163 C164: library part CMP-13271-001123-1, "CAP CER 4.7UF 50V X7R 1206", Capacitance=4.7μF, Case Code (Imperial)=1206, Case Code (Metric)=3216, Dielectric=X7R, Manufacturer=SAMSUNG, Max Operating Temperature=125°C, Min Operating Temperature=-55°C, Package Quantity=1, Tolerance=10%, Voltage Rating=50V
C168: "CAP CER 0.047UF 50V X7R 0603", Capacitance=47nF, Case Code (Imperial)=0603, Case Code (Metric)=1608, Dielectric=X7R, Manufacturer=TDK, Max Operating Temperature=125°C, Min Operating Temperature=-55°C, Package Quantity=1, Ratings=AEC-Q200, Supplier Part Number 1=80X3178, Tolerance=10%, Voltage Rating=50V
C171: "CAP CER 0.22UF 25V X7R 0603", Capacitance=220nF, Case Code (Imperial)=0603, Case Code (Metric)=1608, Dielectric=X7R, Manufacturer=MURATA, Max Operating Temperature=125°C, Min Operating Temperature=-55°C, Package Quantity=1, Ratings=AEC-Q200, Supplier Part Number 1=81-GCM188R71E224K55D, Tolerance=10%, Voltage=25V
C172 C189 C190: "CAP CER 0.1UF 50V X7R 0603", Capacitance=100nF, Case Code (Imperial)=0603, Case Code (Metric)=1608, Dielectric=X7R, Manufacturer=TDK, Max Operating Temperature=125°C, Min Operating Temperature=-55°C, Package Quantity=1, Ratings=AEC-Q200, Tolerance=10%, Voltage=50V
C173 C176: "CAP CER 47PF 100V C0G/NP0 0603", Capacitance=47pF, Case Code (Imperial)=0603, Case Code (Metric)=1608, Dielectric=C0G, Dielectric Material=Ceramic, Manufacturer=KEMET, Max Operating Temperature=125°C, Min Operating Temperature=-55°C, Package Quantity=4000, Supplier Part Number 1=8015369, Temperature Coefficient=30ppm/°C, Tolerance=5%, Voltage=100V
C185 C194: "CAP CER 680PF 50V C0G/NP0 0603", Capacitance=680pF, Case Code (Imperial)=0603, Case Code (Metric)=1608, Dielectric=C0G, Dielectric Material=Ceramic, Manufacturer=KEMET, Max Operating Temperature=125°C, Min Operating Temperature=-55°C, Package Quantity=4000, Supplier Part Number 1=80-C0603C681J5G, Temperature Coefficient=30ppm/°C, Tolerance=5%, Voltage=50V
D1: "LED RED DIFFUSED 0805 SMD", Case Code (Imperial)=0805, Case Code (Metric)=2012, Color=RED, Forward Current=20mA, Forward Voltage=2V, Illumination Color=Red, Manufacturer="VISUAL COMMUNICATIONS", Max Operating Temperature=85°C, Min Operating Temperature=-40°C, Package Quantity=1, Power Rating=100mW, Reverse Voltage=5V, Supplier Part Number 1=45X6246
D2: "LED YELLOW CLEAR 0805 SMD", Case Code (Imperial)=0805, Case Code (Metric)=2012, Color=Yellow, Forward Current=30mA, Forward Voltage=2V, Lens Color=Colorless, Manufacturer=LITE-ON, Max Operating Temperature=85°C, Max Power Dissipation=75mW, Min Operating Temperature=-55°C, Package Quantity=1, Reverse Voltage=5V, Supplier Part Number 1=6920950, Test Current=20mA
D3 D4 D5 D6 D7: library part CMP-22017-000007-1, "LED GREEN CLEAR CHIP SMD", Case Code (Imperial)=0805, Case Code (Metric)=2012, Color=GREEN, Forward Current=30mA, Forward Voltage=2.1V, Illumination Color=Green, Lens Color=Colorless, Manufacturer=LITE-ON, Max Operating Temperature=85°C, Min Operating Temperature=-55°C, Package Quantity=1, Power Dissipation=100mW, Reverse Voltage=5V, Test Current=10mA
D8 D9 D10: "DIODE ARRAY SCHOTTKY 40V SOT363", Manufacturer="MICRO COMMERCIAL", Manufacturer Print=MICRO, Manufacturer_Name="Micro Commercial Components (MCC)", Package=SOT-363
D11 D15: "LED PURPLE CLEAR 1206 SMD", Color=PURPLE, Manufacturer=Kingbright, Manufacturer Print=KINGBRIGHT, Package=1206, Supplier Part Number 1=604-APTR3216-VFX
D12 D16: "LED PURPLE CLEAR 1206 SMD", Color=PURPLE, Manufacturer=KINGBRIGHT, Package=1206, Supplier Part Number 1=604-APTR3216-VFX
D13 D14 D17 D18: "DIODE SCHOTTKY 60V 2A SOD123FL", Average Rectified Current=2A, Forward Voltage=700mV, Manufacturer=MICRO, Max Operating Temperature=125°C, Max Power Dissipation=1.68W, Max Repetitive Reverse Voltage (Vrrm)=60V, Max Reverse Current=500uA, Max Surge Current=50A, Min Operating Temperature=-65°C, Package=SOD-123F, Package Quantity=1, Supplier Part Number 1=SMD26PL-TPMSCT-ND
D19 D20: "DIODE SCHOTTKY 60V 10A CFP15B", Case/Package=TO-277, Manufacturer=NEXPERIA
HS1: library part "LA 6 150 12", "HEATSINK EXTRUSION 150MM", Manufacturer="FISCHER ELEKTRONIK", Natural Thermal Resistance=0.175°C/W, Package=N/A, Power Consumption=2.9W, Supplier Part Number 1=42M1958
J1: "TERM BLOCK HDR 6POS VERT 5.08MM", Color=Green,Grey, Current=12A, Flammability Rating="UL94 V-0", Housing Color=Green, Manufacturer="PHOENIX CONTACT", Package=N/A, Package Quantity=50, Supplier Part Number 1=1896240, Voltage=300V, Voltage Rating=250V
J2 J3 J18 J19 J20: "TERM REDCUBE M4 8PIN PCB", Current Rating=80A, Manufacturer="WURTH ELEKTRONIK", Manufacturer Print=WURTH, Max Operating Temperature=135°C, Min Operating Temperature=-40°C, Package=N/A, Package Quantity=250, Supplier Part Number 1=1224952
J4: "CONN D-SUB PLUG 9POS R/A SLDR", Color=Black, Current Rating=5A, Manufacturer=AMPHENOL, Max Operating Temperature=155°C, Max Supply Voltage (AC)=250V, Min Operating Temperature=-55°C, Package=N/A, Supplier Part Number 1=70145033
J5: library part CMP-2000-05419-1, "CONN HEADER VERT 4POS 2.54MM", Color=White, Current, Rating="5 /  / A", Flammability Rating=UL94V-0, Manufacturer=TE, Package=N/A, Temperature, Operating="-55to+105 /  / degC", Voltage, Rating="250 /  / V"
J6 J7 J8 J13 J14 J15: "CONN MMCX JACK STR 50 OHM PCB", Manufacturer=MOLEX, Manufacturer Part Number=73415-1471, Max Frequency=6GHz, Operating Frequency=N/A, Package Quantity=500, Supplier Part Number 1=70364031
J9: "CONN HEADER VERT 12POS 2.54MM", Color=Black, Flammability Rating="UL94 V-0", Manufacturer="WURTH ELEKTRONIK", Manufacturer Print=WURTH, Max Operating Temperature=105°C, Min Operating Temperature=-40°C, Package=N/A, Supplier Part Number 1=732-5297-ND, Voltage Rating=250V
J10 J11: "TERM BLOCK HDR 2POS VERT 2.5MM", Manufacturer="PHOENIX CONTACT", Package=N/A
J12 J16: "TERM BLOCK HDR 2POS VERT 5.08MM", Colour=Green, Manufacturer="PHOENIX CONTACT", Package=N/A, Supplier Part Number 1=1896199
J17: library part CMP-1502-00000-1, "CONN HEADER VERT 6POS 2.54MM", Contact Resistance=20mOhm, Manufacturer="WURTH ELECTRONIK", Operating Temperature=-40to125degC, Package=N/A, Withstanding Voltage=500VAC, Working Voltage=250VAC
J21: "CONN PWR JACK 2X5.5MM SOLDER", Color=Black, Current Rating=5A, Flammability Rating="UL94 V-0", Insulation Resistance=50MR, Manufacturer="CUI DEVICES", Max Operating Temperature=85°C, Min Operating Temperature=-25°C, Package=N/A, Package Quantity=280, Voltage Rating=24V
J22: "TERM BLOCK HDR 2POS 90DEG 2.5MM", Manufacturer="PHOENIX CONTACT", Package=N/A
L1 L2 L3 L4 L5 L6: "CMC 10UH 1.6A 2LN 920 OHM SMD", Case/Package=SMD/SMT, Current=1.6A, DC Resistance (DCR)=80mR, Inductance=10uH, Manufacturer="WURTH ELECTRONIK", Manufacturer Print=WURTH, Max Operating Temperature=125°C, Min Operating Temperature=-40°C, Package=4-PC, Package Quantity=1, Supplier Part Number 1=9040408, Test Frequency=1kHz, Tolerance=30%, Voltage Rating=80V
L7: "FIXED IND 10UH 5.8A 20 MOHM SMD", Case/Package=N/A, Manufacturer="WURTH ELECTRONIK"
L8 L9: "FIXED IND 22UH 3.5A 74 MOHM SMD", Ambient Temperature Range High=85°C, Ambient Temperature Range Low=-40°C, DC Resistance (DCR)=64mΩ, Inductance=22µH, Inductance Tolerance=20%, Manufacturer="WURTH ELECTRONIK", Max Operating Temperature=125°C, Package=N/A, RMS Current (Irms)=3.5A, Saturation Current=5A, Self Resonant Frequency=7MHz, Series Resistance=74mΩ, Test Frequency=100kHz
L10: library part CMP-006-00021-3, "CMC 100UH 200MA 2LN SMD AEC-Q200", Manufacturer=MURATA, Max Operating Temperature=125°C, Min Operating Temperature=-40°C, Package=4-SMD
MH1 MH2 MH3 MH4: "HEX STANDOFF M4 ALUMINUM 51MM F-F", Manufacturer=MCMASTER-CARR, Manufacturer Part Number=95947A552, Package=N/A
Q1: library part CMP-1048-00731-1, "TRANS NPN 45V 0.5A SOT23-3", Manufacturer=ONSEMI, Package=SOT-23-3
Q2: library part CCB021M12FM3, "SIC 6N-CH 1200V 30A MODULE", Manufacturer=WOLFSPEED, Mfr_Name="Cree Wolfspeed", Package=FMC
Q3 Q4: library part CMP-12801-000047-1, "MOSFET N-CH 60V 1.6A SOT23", Continuous Drain Current=1.6A, Drain To Source Breakdown Voltage=60V, Drain To Source Resistance=92mΩ, Gate To Source Voltage=20V, Input Capacitace At Vds="315pF @ 40V", Manufacturer="DIODES INC.", Max Forward Diode Voltage=1V, Max Junction Temp=+150°C, Package=SOT23, Power Dissipation=0.7W, Pulse Drain Current=10A, Temperature="-55°C to +150°C", Temperature Range Low=-55°C, Typ Forward Diode Voltage=0.75V
Q5 Q6: library part CMP-1046-00010-1, "TRANS NPN 80V 8A DPAK", Manufacturer=ONSEMI, Package=TO-252-3
Q7 Q8: "MOSFET N-CH 120V 90A PWRDI5060-8", Manufacturer="DIODES INC", Package=8-PowerTDFN, Supplier Part Number 1=68AH9585
R1 R2 R3 R4 R5 R6 R7 R8 R9 R10 R11 R12: library part CMP-03211-002966-1, "RES 220K OHM 1% 2W 2512", Ambient Temperature Range High=+70°C, Manufacturer=TE, Package=2512, Power Rating=2W, Resistance=220kΩ, Temperature="-55°C to +155°C", Temperature Coefficient=±100ppm/°C, Temperature Range High=+155°C, Temperature Range Low=-55°C, Tolerance=0.01, Voltage Rating=500V
R13 R14 R15 R16 R17 R18 R19 R20 R21 R22 R23 R24 R25 R26 R27 R28 R29 R30 R31 R32 R33 R34 R35 R36 R157 R158 R159 R160 R161 R162 R163 R164 R165 R166 R167 R168 R169 R170 R171 R172 R173 R174 R175 R176 R177 R178 R179 R180: library part CMP-2003-04604-1, "RES 249K OHM 0.1% 1/4W 1206", Manufacturer="VISHAY DALE", Package=1206, Power=0.25W, Resistance=249kΩ
R37 R39 R41 R43 R182 R185 R188 R191: "RES 4.99K OHM 1% 1/10W 0603", Case Code (Imperial)=0603, Case Code (Metric)=1608, Manufacturer=YAGEO, Max Operating Temperature=155°C, Max Power Dissipation=0.1W, Min Operating Temperature=-55°C, Package Quantity=1, Resistance=4.99kΩ, Resistance Tolerance=1%, Resistor Type="Thick Film", Supplier Part Number 1=1995595, Temperature Coefficient=100ppm/°C, Voltage Rating=75V, Voltage Rating (DC)=50V
R38 R190: "RES SMD 3.74K OHM 0.1% 1/5W 0603", Case Code (Imperial)=0603, Case Code (Metric)=1608, Manufacturer=PANASONIC, Max Operating Temperature=155°C, Max Power Dissipation=0.2W, Min Operating Temperature=-55°C, Resistance=3.74kΩ, Resistor Type="Thick Film", Temperature Coefficient=50ppm/°C, Tolerance=0.1%
R40 R42 R44 R251 R256 R260 R263: "RES SMD 4.7K OHM 1% 1/10W 0603", Case Code (Imperial)=0603, Case Code (Metric)=1608, Manufacturer="VISHAY DALE", Max Operating Temperature=155°C, Max Power Dissipation=100mW, Min Operating Temperature=-55°C, Package Quantity=5000, Power Rating=0.1W, Resistance=4.7kΩ, Resistor Type="Thick Film", Supplier Part Number 1=541-3004-6-ND, Temperature Coefficient=100ppm/°C, Tolerance=1%, Voltage Rating=75V
R45 R46 R64 R65 R66 R71 R87 R89 R90 R93 R94 R95 R102 R108 R120 R121 R135 R138 R139 R141 R197 R198 R220 R223 R228 R235 R236 R252 R258 R261 R266 R270 R272: "RES SMD 10K OHM 1% 1/10W 0603", Case Code (Imperial)=0603, Case Code (Metric)=1608, Manufacturer=PANASONIC, Manufacturer Part Number=ERJ-3EKF1002V, Max Operating Temperature=155°C, Max Power Dissipation=0.1W, Min Operating Temperature=-55°C, Package Quantity=1, Power Rating=100mW, Resistance=10kΩ, Resistance Tolerance=1%, Resistor Type="Thick Film", Supplier Part Number 1=1051156, Temperature Coefficient=100ppm/°C, Voltage Rating=75V
R47 R48 R49 R50 R76 R79 R82 R84 R85 R183 R186 R189 R192 R226 R227 R229 R232 R233 R234 R237 R238: "RES SMD 0 OHM JUMPER 1/10W 0603", Case Code (Imperial)=0603, Case Code (Metric)=1608, Manufacturer="VISHAY DALE", Manufacturer Part Number=CRCW06030000Z0EBC, Max Operating Temperature=155°C, Max Power Dissipation=100mW, Min Operating Temperature=-55°C, Package Quantity=10000, Ratings=AEC-Q200, Resistance=0Ω, Resistor Type="Thick Film", Supplier Part Number 1=48P7902, Temperature Coefficient=100ppm/°C, Tolerance=1%, Voltage Rating=75V
R51 R52 R54 R57 R59 R63 R69 R70 R72 R73 R83 R99 R100 R103 R104 R126 R127 R129 R130 R206 R209 R241 R242: "RES SMD 49.9 OHM 1% 1/10W 0603", Case Code (Imperial)=0603, Case Code (Metric)=1608, Manufacturer=PANASONIC, Max Operating Temperature=155°C, Max Power Dissipation=100mW, Min Operating Temperature=-55°C, Package Quantity=5000, Power Rating=0.1W, Resistance=49.9Ω, Resistance Tolerance=1%, Resistor Type="Thick Film", Supplier Part Number 1=12AC1058, Temperature Coefficient=100ppm/°C, Voltage Rating=75V, Voltage Rating (DC)=50V, Working Voltage=6V
R53: "RES 2.2K OHM 1% 1/10W 0603", Manufacturer=YAGEO, Package=0603, Power=0.1W
R55 R181 R184 R187: "RES SMD 1.8K OHM 0.1% 1/5W 0603", Case Code (Imperial)=0603, Case Code (Metric)=1608, Manufacturer=PANASONIC, Max Operating Temperature=155°C, Max Power Dissipation=0.2W, Min Operating Temperature=-55°C, Resistance=1.8kΩ, Resistor Type="Thick Film", Temperature Coefficient=50ppm/°C, Tolerance=0.1%
R56 R58 R61: "RES SMD 4.02KOHM 0.1% 1/10W 0603", Case Code (Imperial)=0603, Case Code (Metric)=1608, Manufacturer=PANASONIC, Manufacturer Part Number=ERA-3AEB4021V, Max Operating Temperature=155°C, Max Power Dissipation=100mW, Min Operating Temperature=-55°C, Package Quantity=1, Resistance=4.02kΩ, Resistance Tolerance=0.1%, Resistor Type="Thin Film", Supplier Part Number 1=7087616, Temperature Coefficient=25ppm/°C, Voltage Rating=75V
R60 R62 R114 R122 R128 R151 R255: "RES SMD 2K OHM 0.5% 1/10W 0603", Case Code (Imperial)=0603, Case Code (Metric)=1608, Manufacturer=YAGEO, Max Operating Temperature=125°C, Max Power Dissipation=100mW, Min Operating Temperature=-55°C, Package Quantity=5000, Power Rating=0.1W, Resistance=2kΩ, Resistor Type="Thin Film", Supplier Part Number 1=6165116, Temperature Coefficient=50ppm/°C, Tolerance=0.5%, Voltage Rating=75V, Voltage Rating (DC)=50V
R67 R75 R97 R106 R123 R132 R133 R134: "RES SMD 0 OHM JUMPER 3/4W 1210", Case Code (Imperial)=1210, Case Code (Metric)=3225, Manufacturer="VISHAY DALE", Max Operating Temperature=155°C, Max Power Dissipation=750mW, Min Operating Temperature=-55°C, Package Quantity=10, Power Rating=0.75W, Resistance=0Ω, Supplier Part Number 1=71-CRCW12100000Z0EAH
R68 R74 R98 R105 R124 R131: library part CMP-2005-02198-1, "RES 0.91 OHM 1% 1W 1210", Manufacturer="VISHAY DALE", Package=1210, Power=1W
R77 R78 R80 R81 R115 R116 R118 R119 R243 R244 R245 R246 R248: "RES 249 OHM 1% 1/4W 1206", Case Code (Imperial)=1206, Case Code (Metric)=3216, Manufacturer=YAGEO, Max Operating Temperature=155°C, Max Power Dissipation=250mW, Min Operating Temperature=-55°C, Power Rating=0.25W, Resistance=249Ω, Resistor Type="Thick Film", Supplier Part Number 1=1142064, Temperature Coefficient=100ppm/°C, Tolerance=1%, Voltage Rating=200V
R86 R142: "RES 5.49K OHM 1% 1/10W 0603", Case Code (Imperial)=0603, Case Code (Metric)=1608, Manufacturer=YAGEO, Max Operating Temperature=155°C, Max Power Dissipation=100mW, Min Operating Temperature=-55°C, Package Quantity=5000, Power Rating=0.1W, Resistance=5.49kΩ, Supplier Part Number 1=1172345, Temperature Coefficient=100ppm/°C, Tolerance=1%, Voltage Rating=50V
R88 R221 R222 R224 R225 R230 R231: "RES 330 OHM 1% 1/10W 0603", Case Code (Imperial)=0603, Case Code (Metric)=1608, Manufacturer=YAGEO, Max Operating Temperature=155°C, Min Operating Temperature=-55°C, Power Rating=0.1W, Resistance=330Ω, Resistor Type="Thick Film", Supplier Part Number 1=4067719, Temperature Coefficient=100ppm/°C, Tolerance=1%, Voltage Rating=50V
